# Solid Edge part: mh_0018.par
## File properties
Title: glip_l_b
Author: edge
Template: normal.par
Last saved by: edge
Revision: 30
Application: Solid Edge
Material: ABS
非切断部品: False
文書内容のタイプ: 0
Density: 0.001200 g/mm^3
Accuracy: 0.99
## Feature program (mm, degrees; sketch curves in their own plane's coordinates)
sketch for "unnamed Protrusion 1" plane through (0, 0, 0) normal (0, 0, 1) x-axis (1, 0, 0)
  line (0, 0) -> (50, 0)
  line (50, 0) -> (50, -80)
  line (50, -80) -> (0, -80)
  line (0, -80) -> (0, 0)
extrude "unnamed Protrusion 1" add finite 15 along -normal
thinwall "Thinwall_1"  Thickness = 1 mm
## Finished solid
Body 1: solid body, 11 faces, 24 edges, 16 vertices.
  Faces by surface: plane 11
  Edges by curve: line 24
Bounding box of the edges (mm): 50.000 x 80.000 x 15.000, from (0, -80, -15) to (50, 0, 0).
Planar faces by outward normal: +x 2, +y 2, +z 2, -x 2, -y 2, -z 1
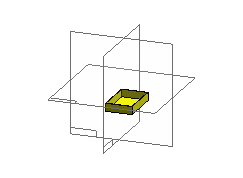
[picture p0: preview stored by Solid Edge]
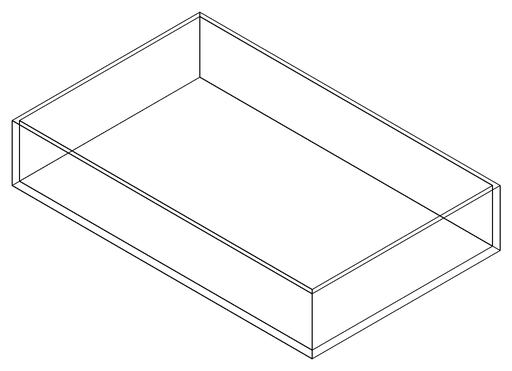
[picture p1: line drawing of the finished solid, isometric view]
